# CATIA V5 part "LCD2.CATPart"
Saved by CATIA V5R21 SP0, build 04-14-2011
Part number: LCD
Bounding box of the stored display mesh (mm): x -92.8 to 92.8, y -50 to 50, z 0 to 2.8
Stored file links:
  C:\Users\Pouria\Desktop\Box\LCD2.CATPart
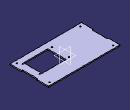
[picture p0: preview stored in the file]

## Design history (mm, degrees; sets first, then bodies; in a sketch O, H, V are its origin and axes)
Body1 (main body)
  Sketch1 on xy-plane, origin (0, 0, 0), H (1, 0, 0), V (0, 1, 0)
    line L1 (92.8, 50) -> (92.8, 20)
    line L2 (92.8, -50) -> (-92.8, -50)
    line L3 (-92.8, -50) -> (-92.8, -20)
    line L4 (-92.8, 50) -> (92.8, 50)
    point P1 (92.8, 50)
    point P2 (92.8, -50)
    line L5 (9.8, 13) -> (72.8, 13)
    line L6 (72.8, 13) -> (72.8, -35)
    line L7 (72.8, -35) -> (9.8, -35)
    line L8 (9.8, -35) -> (9.8, 13)
    line L9 (92.8, 20) -> (90, 20)
    line L10 (90, 20) -> (90, -20)
    line L11 (90, -20) -> (92.8, -20)
    point P12 (92.8, -20)
    point P13 (-92.8, 20)
    line L12 (-92.8, 20) -> (-90, 20)
    line L13 (-90, 20) -> (-90, -20)
    line L14 (-90, -20) -> (-92.8, -20)
    line L15 (92.8, -20) -> (92.8, -50)
    line L16 (-92.8, 20) -> (-92.8, 50)
    circle A1 centre (82.5, -42.5) radius 1.5
    point P17 (82.5, -42.5)
    circle A2 centre (82.5, 42.5) radius 1.5
    point P18 (82.5, 42.5)
    circle A3 centre (-82.5, 42.5) radius 1.5
    point P19 (-82.5, 42.5)
    circle A4 centre (-82.5, -42.5) radius 1.5
    point P20 (-82.5, -42.5)
    length L4 = 185.6
    length L5 = 63
    length L6 = 48
    distance L2 L7 = 15
    length L9 = 2.8
    length L13 = 40
    distance P1 P2 = 100
    distance L1 L6 = 20
    distance P17 L2 = 7.5
    distance P17 L10 = 7.5
    distance P20 L13 = 7.5
    distance P20 L2 = 7.5
    distance P19 L4 = 7.5
    distance P19 L13 = 7.5
    distance P18 L4 = 7.5
    distance P18 L10 = 7.5
    radius A2 = 1.5
    radius A3 = 1.5
    radius A4 = 1.5
    radius A1 = 1.5
    vertical: L1 V, L3 V, L6 V, L8 V, L10 V, L13 V, L15 V, L16 V
    horizontal: L2 H, L4 H, L5 H, L7 H, L9 H, L11 H, L12 H, L14 H
    equidistance: L1 L3 O, L2 L4 O
    coincidence: P12 L1, P13 L3, L9 L12, L11 L14, L1 L15, L3 L16
    symmetry: L12 L14 H, L11 L9 H, L10 L13 V
  Pad1: profile Sketch1, direction (0, 0, 1), length 2.8
  Sketch2 on end face of Pad1, origin (0, 0, 2.8), H (1, 0, 0), V (0, 1, 0)
    circle A1 centre (76.55, -33.1) radius 1.6
    point P1 (76.55, -33.1)
    circle A2 centre (0.65, -33.1) radius 1.6
    point P2 (0.65, -33.1)
    circle A3 centre (0.65, 11.1) radius 1.6
    point P3 (0.65, 11.1)
    circle A4 centre (76.55, 11.1) radius 1.6
    point P4 (76.55, 11.1)
    radius A4 = 1.6
    radius A1 = 1.6
    radius A3 = 1.6
    radius A2 = 1.6
    distance P3 V = 0.65
    distance P3 H = 11.1
    distance P2 V = 0.65
    distance P2 H = 33.1
    distance P1 V = 76.55
    distance P1 H = 33.1
    distance P4 V = 76.55
    distance P4 H = 11.1
  Pocket1: profile Sketch2, direction (0, 0, -1), through (limit type 6)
